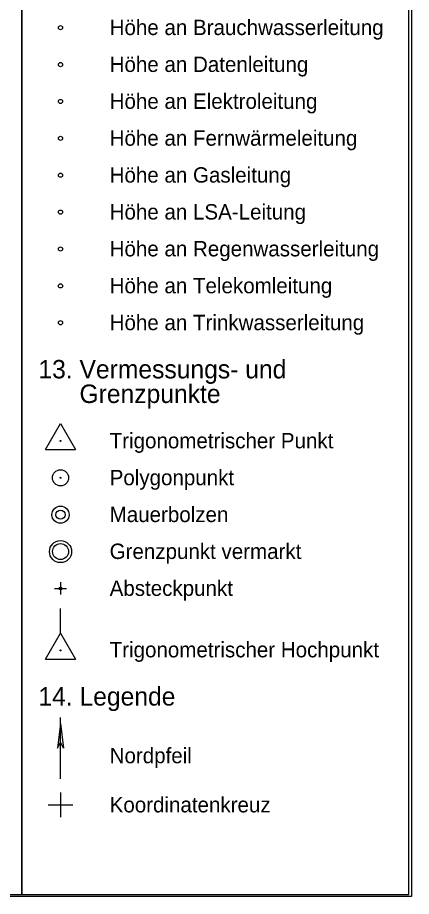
# Model space of a CAD drawing. Extents: x 679244 to 679420, y 5639809 to 5639932.
# Drawn here: x 679387.9 to 679420, y 5639808.5 to 5639880 of the extents above; entities that cross this region are included whole.
import ezdxf

# ---------------------------------------------------------------- set-up
doc = ezdxf.new("R2010")
doc.units = 0
for name, color, linetype in [('Absteckpunkt', 7, 'Continuous'), ('Default', 7, 'Continuous'), ('Grenz_vermarkt', 7, 'Continuous'), ('Hoehe_bw_symbol', 7, 'Continuous'), ('Hoehe_daten_symb', 7, 'Continuous'), ('Hoehe_el_symbol', 7, 'Continuous'), ('Hoehe_fw_symbol', 7, 'Continuous'), ('Hoehe_gas_symbol', 7, 'Continuous'), ('Hoehe_lsa_symbol', 7, 'Continuous'), ('Hoehe_rw_symbol', 7, 'Continuous'), ('Hoehe_tel_symbol', 7, 'Continuous'), ('Hoehe_tw_symbol', 7, 'Continuous'), ('Koordinatenkreuz', 7, 'Continuous'), ('MB', 7, 'Continuous'), ('Nordpfeil', 7, 'Continuous'), ('PP', 7, 'Continuous'), ('Rahmen_1', 7, 'Continuous'), ('TP', 7, 'Continuous'), ('TP_hoch', 7, 'Continuous')]:
    doc.layers.add(name, color=color, linetype=linetype)

msp = doc.modelspace()

# ---------------------------------------------------------------- linework, layer by layer
at = {"layer": 'Absteckpunkt'}
for points in [[(679391.427, 5639834.061), (679391.427, 5639833.061)], [(679390.927, 5639833.561), (679391.927, 5639833.561)]]:
    msp.add_lwpolyline(points, dxfattribs=at)
msp.add_circle((679391.427, 5639833.561), 0.1, dxfattribs=at)
at = {"layer": 'Default'}
for points in [[(679360.286, 5639808.666), (679388.286, 5639808.666), (679388.286, 5639928.666), (679360.286, 5639928.666)], [(679388.286, 5639808.666), (679419.79, 5639808.666), (679419.79, 5639928.666), (679388.286, 5639928.666)]]:
    msp.add_lwpolyline(points, close=True, dxfattribs=at)
at = {"layer": 'Grenz_vermarkt'}
for radius in [0.9, 0.65]:
    msp.add_circle((679391.427, 5639836.561), radius, dxfattribs=at)
at = {"layer": 'Hoehe_bw_symbol'}
msp.add_circle((679391.427, 5639879.171), 0.171, dxfattribs=at)
at = {"layer": 'Hoehe_daten_symb'}
msp.add_circle((679391.427, 5639876.171), 0.171, dxfattribs=at)
at = {"layer": 'Hoehe_el_symbol'}
msp.add_circle((679391.427, 5639873.171), 0.171, dxfattribs=at)
at = {"layer": 'Hoehe_fw_symbol'}
msp.add_circle((679391.427, 5639870.171), 0.171, dxfattribs=at)
at = {"layer": 'Hoehe_gas_symbol'}
msp.add_circle((679391.427, 5639867.171), 0.171, dxfattribs=at)
at = {"layer": 'Hoehe_lsa_symbol'}
msp.add_circle((679391.427, 5639864.171), 0.171, dxfattribs=at)
at = {"layer": 'Hoehe_rw_symbol'}
msp.add_circle((679391.427, 5639861.171), 0.171, dxfattribs=at)
at = {"layer": 'Hoehe_tel_symbol'}
msp.add_circle((679391.427, 5639858.171), 0.171, dxfattribs=at)
at = {"layer": 'Hoehe_tw_symbol'}
msp.add_circle((679391.427, 5639855.171), 0.171, dxfattribs=at)
at = {"layer": 'Koordinatenkreuz'}
for points in [[(679391.427, 5639816.974), (679391.427, 5639814.974)], [(679390.427, 5639815.974), (679392.427, 5639815.974)]]:
    msp.add_lwpolyline(points, dxfattribs=at)
at = {"layer": 'MB'}
for radius in [0.7, 0.37]:
    msp.add_circle((679391.427, 5639839.561), radius, dxfattribs=at)
at = {"layer": 'Nordpfeil'}
msp.add_line((679391.427, 5639818.074), (679391.427, 5639823.074), dxfattribs=at)
for points in [[(679391.427, 5639822.574), (679391.177, 5639820.574), (679391.427, 5639821.074)], [(679391.427, 5639822.574), (679391.677, 5639820.574), (679391.427, 5639821.074)]]:
    msp.add_lwpolyline(points, close=True, dxfattribs=at)
at = {"layer": 'PP'}
msp.add_line((679391.427, 5639842.561), (679391.427, 5639842.561), dxfattribs=at)
for radius in [0.66, 0.041]:
    msp.add_circle((679391.427, 5639842.561), radius, dxfattribs=at)
at = {"layer": 'Rahmen_1'}
msp.add_lwpolyline([(679419.991, 5639808.515), (679243.507, 5639808.515), (679243.507, 5639931.667), (679419.991, 5639931.667)], close=True, dxfattribs=at)
at = {"layer": 'TP'}
for p, q in [((679390.196, 5639844.855), (679391.416, 5639846.969)), ((679391.416, 5639846.969), (679392.635, 5639844.855)), ((679391.427, 5639845.561), (679391.427, 5639845.561)), ((679390.196, 5639844.855), (679392.635, 5639844.855))]:
    msp.add_line(p, q, dxfattribs=at)
msp.add_circle((679391.427, 5639845.561), 0.037, dxfattribs=at)
at = {"layer": 'TP_hoch'}
for p, q in [((679391.416, 5639829.932), (679391.416, 5639831.942)), ((679390.196, 5639827.818), (679391.416, 5639829.932)), ((679391.416, 5639829.932), (679392.635, 5639827.818)), ((679391.427, 5639828.524), (679391.427, 5639828.524)), ((679390.196, 5639827.818), (679392.635, 5639827.818))]:
    msp.add_line(p, q, dxfattribs=at)
msp.add_circle((679391.427, 5639828.524), 0.037, dxfattribs=at)

# ---------------------------------------------------------------- texts
at = {"layer": 'Default'}
for s, height, p in [('Höhe an Brauchwasserleitung', 1.25, (679395.427, 5639878.569)), ('Höhe an Datenleitung', 1.25, (679395.427, 5639875.569)), ('Höhe an Elektroleitung', 1.25, (679395.427, 5639872.569)), ('Höhe an Fernwärmeleitung', 1.25, (679395.427, 5639869.569)), ('Höhe an Gasleitung', 1.25, (679395.427, 5639866.569)), ('Höhe an LSA-Leitung', 1.25, (679395.427, 5639863.569)), ('Höhe an Regenwasserleitung', 1.25, (679395.427, 5639860.569)), ('Höhe an Telekomleitung', 1.25, (679395.427, 5639857.569)), ('Höhe an Trinkwasserleitung', 1.25, (679395.427, 5639854.569)), ('13. Vermessungs- und ', 1.5, (679389.628, 5639850.646)), ('      Grenzpunkte', 1.5, (679389.628, 5639848.646)), ('Trigonometrischer Punkt', 1.25, (679395.427, 5639844.959)), ('Polygonpunkt', 1.25, (679395.427, 5639841.959)), ('Mauerbolzen', 1.25, (679395.427, 5639838.959)), ('Grenzpunkt vermarkt', 1.25, (679395.427, 5639835.959)), ('Absteckpunkt', 1.25, (679395.427, 5639832.959)), ('Trigonometrischer Hochpunkt', 1.25, (679395.427, 5639827.959)), ('14. Legende    ', 1.5, (679389.628, 5639824.036)), ('Nordpfeil', 1.25, (679395.427, 5639819.349)), ('Koordinatenkreuz', 1.25, (679395.427, 5639815.349))]:
    msp.add_text(s, height=height, dxfattribs=at).set_placement(p)

doc.saveas('drawing.dxf')
